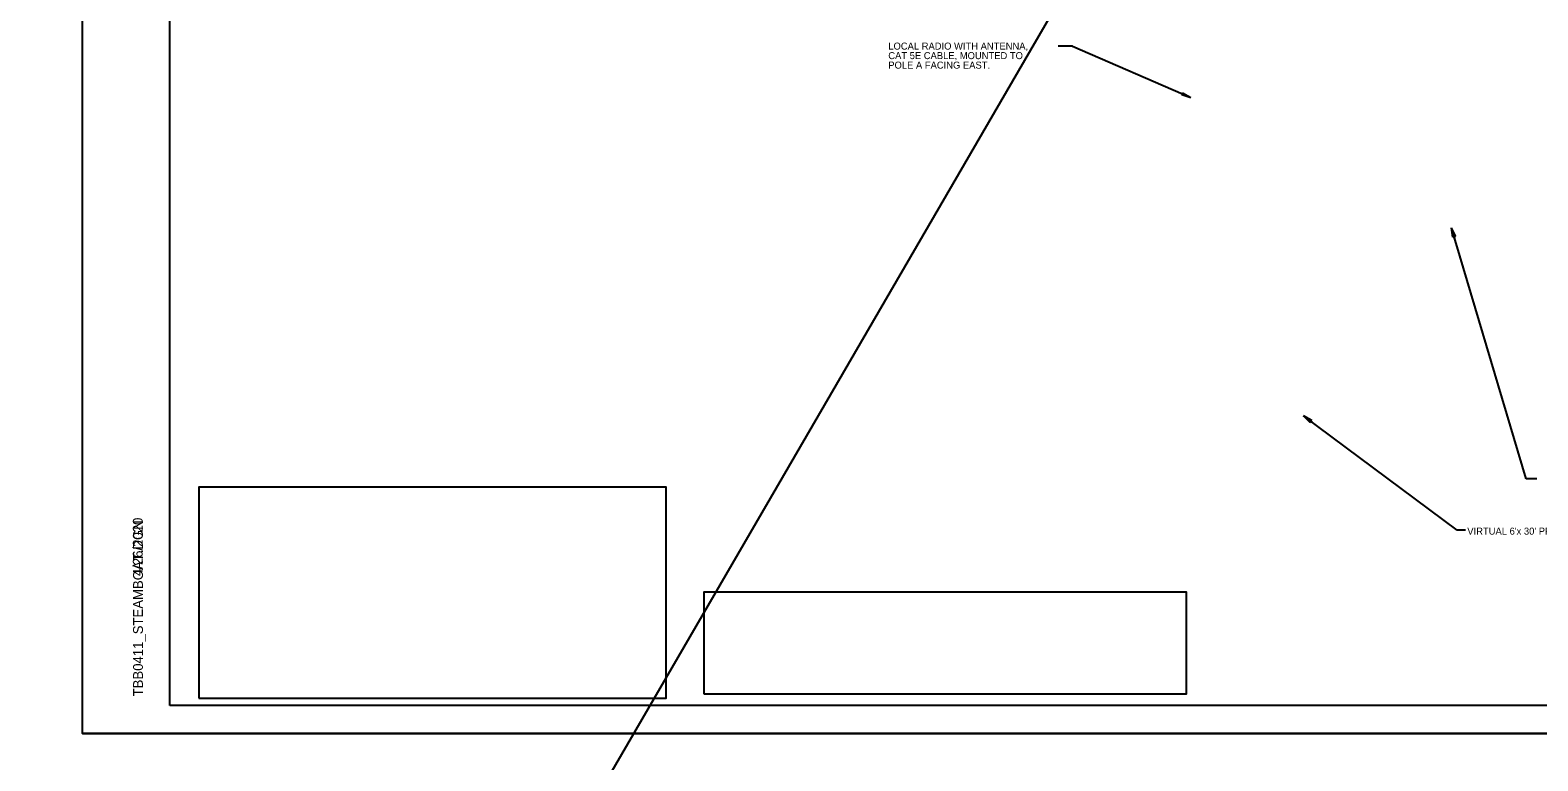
# Model space of a CAD drawing. Extents: x 660636 to 661659, y 641779 to 643841.
# Drawn here: x 660636 to 661280, y 642272 to 642585 of the extents above; entities that cross this region are included whole.
import ezdxf

# ---------------------------------------------------------------- set-up
doc = ezdxf.new("R2010")
doc.units = 0
for name, color, linetype in [('Default', 7, 'Continuous'), ('R_Border', 7, 'Continuous'), ('R_No Plot', 7, 'Continuous'), ('T_Drafting', 7, 'Continuous')]:
    doc.layers.add(name, color=color, linetype=linetype)

msp = doc.modelspace()

# ---------------------------------------------------------------- linework, layer by layer
at = {"layer": 'Default'}
msp.add_lwpolyline([(660708.16, 642299.12), (660907.81, 642299.12), (660907.81, 642389.39), (660708.16, 642389.39)], close=True, dxfattribs=at)
at = {"layer": 'R_Border'}
for p, q in [((660695.76, 642295.93), (660695.76, 642912.31)), ((660695.76, 642295.93), (660695.76, 642295.93)), ((661644.3, 642295.93), (660695.76, 642295.93))]:
    msp.add_line(p, q, dxfattribs=at)
at = {"layer": 'R_No Plot'}
msp.add_line((660658.55, 642284), (661658.55, 642284), dxfattribs=at)
msp.add_lwpolyline([(660658.53, 642924), (661658.55, 642924), (661658.55, 642283.98), (660658.53, 642283.98)], close=True, dxfattribs=at)
at = {"layer": 'T_Drafting'}
for p, q in [((661081.37, 642577.92), (661075.3, 642577.92)), ((661081.37, 642577.92), (661131.95, 642555.96)), ((661128.42, 642557.88), (661128.14, 642557.23)), ((661128.14, 642557.23), (661131.95, 642555.96)), ((661128.16, 642557.29), (661131.33, 642556.23)), ((661128.18, 642557.34), (661130.7, 642556.5)), ((661128.21, 642557.4), (661130.09, 642556.77)), ((661128.23, 642557.45), (661129.47, 642557.04)), ((661128.26, 642557.51), (661128.86, 642557.3)), ((661128.3, 642557.61), (661128.86, 642557.3)), ((661128.32, 642557.66), (661129.47, 642557.04)), ((661128.35, 642557.72), (661130.09, 642556.77)), ((661128.37, 642557.77), (661130.7, 642556.5)), ((661128.39, 642557.82), (661131.33, 642556.23)), ((661128.42, 642557.88), (661131.95, 642555.96)), ((661275.23, 642392.83), (661243.34, 642500.24)), ((661243.9, 642496.23), (661243.34, 642500.24)), ((661245.05, 642496.57), (661243.34, 642500.24)), ((661244, 642496.26), (661243.53, 642499.6)), ((661244.96, 642496.54), (661243.53, 642499.6)), ((661244.86, 642496.51), (661243.73, 642498.94)), ((661244.1, 642496.29), (661243.73, 642498.94)), ((661244.19, 642496.32), (661243.92, 642498.3)), ((661244.76, 642496.49), (661243.92, 642498.3)), ((661244.67, 642496.46), (661244.11, 642497.65)), ((661244.29, 642496.35), (661244.11, 642497.65)), ((661243.9, 642496.23), (661245.05, 642496.57)), ((661244.57, 642496.43), (661244.3, 642497.01)), ((661244.39, 642496.37), (661244.3, 642497.01)), ((661182.96, 642416.92), (661180.11, 642419.79)), ((661183.68, 642417.88), (661180.11, 642419.79)), ((661245.8, 642370.98), (661180.11, 642419.79)), ((661183.02, 642417), (661180.65, 642419.39)), ((661183.62, 642417.8), (661180.65, 642419.39)), ((661183.56, 642417.72), (661181.2, 642418.98)), ((661183.08, 642417.08), (661181.2, 642418.98)), ((661183.14, 642417.16), (661181.73, 642418.58)), ((661183.5, 642417.64), (661181.73, 642418.58)), ((661183.44, 642417.56), (661182.28, 642418.18)), ((661183.2, 642417.25), (661182.28, 642418.18)), ((661183.38, 642417.48), (661182.81, 642417.78)), ((661183.26, 642417.33), (661182.81, 642417.78)), ((661182.96, 642416.92), (661183.68, 642417.88)), ((661279.83, 642392.83), (661275.23, 642392.83)), ((661249.35, 642370.98), (661245.8, 642370.98))]:
    msp.add_line(p, q, dxfattribs=at)
msp.add_lwpolyline([(661266.39, 643047.99), (661150, 642725.53), (660636.16, 641839.68)], dxfattribs=at)
msp.add_lwpolyline([(661266.39, 643047.99), (661150, 642725.53), (660636.16, 641839.68)], dxfattribs=at)
msp.add_lwpolyline([(661266.39, 643047.99), (661150, 642725.53), (660636.16, 641839.68)], dxfattribs=at)
msp.add_lwpolyline([(660923.97, 642301.01), (661130.14, 642301.01), (661130.14, 642344.41), (660923.97, 642344.41)], close=True, dxfattribs=at)

# ---------------------------------------------------------------- texts
at = {"layer": 'R_Border'}
for s, p in [('4/26/2020', (660684.23, 642351.32)), ('TBB0411_STEAMBOAT.DGN', (660684.33, 642299.91))]:
    msp.add_text(s, height=4.2, rotation=90, dxfattribs=at).set_placement(p)
at = {"layer": 'T_Drafting'}
for s, p in [('CAT 5E CABLE, MOUNTED TO', (661002.73, 642572.31)), ('LOCAL RADIO WITH ANTENNA,', (661002.73, 642576.38)), ('POLE A FACING EAST.', (661002.73, 642568.25)), ("VIRTUAL 6'x 30' PRESENCE VDZ", (661250.07, 642369.04))]:
    msp.add_text(s, height=3, dxfattribs=at).set_placement(p)

doc.saveas('drawing.dxf')
